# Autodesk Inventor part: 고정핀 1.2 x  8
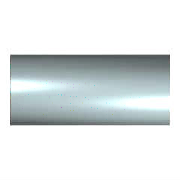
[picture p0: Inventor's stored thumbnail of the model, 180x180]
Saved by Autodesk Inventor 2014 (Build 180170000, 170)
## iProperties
IsCustomPart: 1
Created: 2012-02
Part Number: 고정핀 1.2 x  8
Material: 강철, 연강
Description: 평행 핀
Document SubType Name: Modeling
Standard: KS B 1320
Designer: P15F
Standards Organization: KS
Language: ko-KR
Size Designation: C 1.2 x  8
Categories: <MemberInstance><Categories><Category DisplayName="조임쇠" InternalName="e4da775c-781d-43d5-af7c-5136215cf5a6" Mnemonic="FSTN"><Category DisplayName="핀" InternalNa
Density: 1 g/cm^3
Appearance: 노란색
Author: P15F
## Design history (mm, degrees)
sketch "스케치1"
  geometry: C1 r 0.6 at (0, 0); 1 further point
  constraints: 1 centre point, 1 coincident
  dimensions: "d1" = 1.2 diameter of C1 (= NND)
extrude "본체" new body sketch "스케치1" distance "d2" = 8 (= NLG); taper "d3" = 0 deg
node "작업 평면1"
node "작업 평면2"
body "Solid1"
other parameters: "NND" = 1.2 [user parameter; used in 1 equation term], "NLG" = 8 [user parameter; used in 1 equation term], "d8" = 0, "d9" = 0, "d10" = 0
